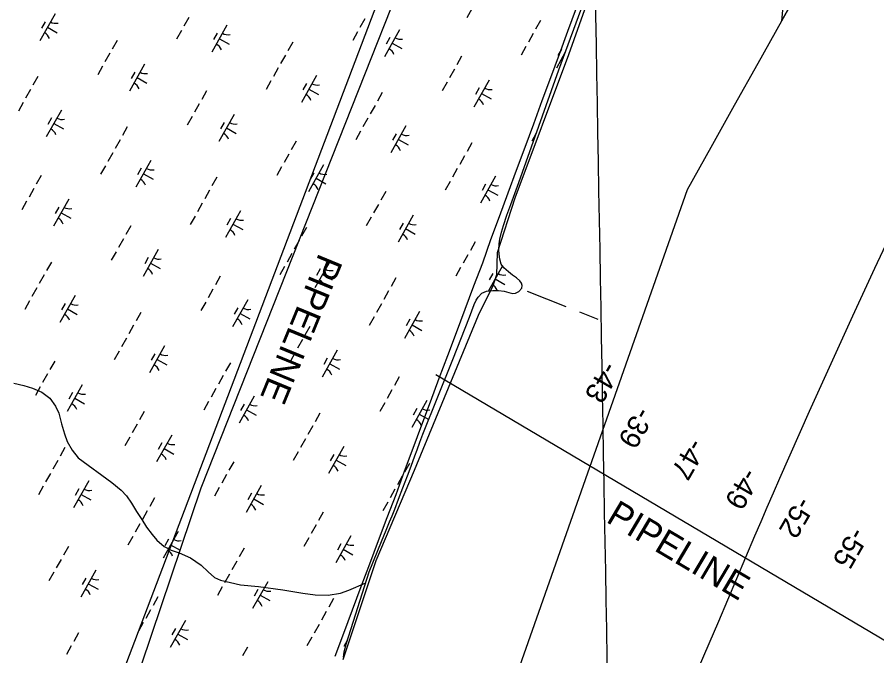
# Model space of a CAD drawing. Extents: x 3913936 to 3933962, y 195330 to 217741.
# Drawn here: x 3924259 to 3925651, y 205982 to 207016 of the extents above; entities that cross this region are included whole.
import ezdxf

# ---------------------------------------------------------------- set-up
doc = ezdxf.new("R2010")
doc.units = 0
for name, color, linetype in [('V-GRID-MAJR', 7, 'Continuous'), ('V-LEVE-TOET', 7, 'Continuous'), ('V-RIVR-EDGE', 7, 'Continuous'), ('V-RIVR-RANG', 7, 'Continuous'), ('V-RRAP-FSHR', 7, 'Continuous'), ('V-TOPO-DPTH', 7, 'Continuous'), ('V-TOPO-MAJR', 7, 'Continuous'), ('V-TOPO-MINR', 7, 'Continuous'), ('V-TOPO-SHOR', 7, 'Continuous'), ('V-UTIL-IDEN', 7, 'Continuous'), ('V-UTIL-LINE', 7, 'Continuous'), ('V-WETL-SWMP', 7, 'Continuous')]:
    doc.layers.add(name, color=color, linetype=linetype)

msp = doc.modelspace()

# ---------------------------------------------------------------- linework, layer by layer
at = {"layer": 'V-GRID-MAJR'}
msp.add_spline([(3925366, 197364), (3925326, 199633.5), (3925219.4, 205693.6), (3925112.7, 211753.6), (3925058.2, 214849.9)], degree=3, dxfattribs=at)
at = {"layer": 'V-LEVE-TOET'}
for p, q in [((3925084.8, 206572.7), (3925147.4, 206548)), ((3925169.6, 206539.2), (3925199.1, 206527.5))]:
    msp.add_line(p, q, dxfattribs=at)
at = {"layer": 'V-RIVR-EDGE'}
msp.add_lwpolyline([(3925251.9, 207238.2), (3925151.7, 206955.3), (3925064.5, 206723.1), (3925036.2, 206634.7), (3925035, 206599.3), (3925029.1, 206581.6), (3925005.6, 206533.3), (3924901.8, 206282.2), (3924839.4, 206136.1), (3924786.3, 205975.8)], dxfattribs=at)
at = {"layer": 'V-RRAP-FSHR'}
for points in [[(3924872.5, 206243.8), (3924886.1, 206281.3), (3924900.2, 206318.7), (3924914.2, 206356.2), (3924928.3, 206393.6), (3924942.3, 206431.8), (3924956.4, 206468.5), (3924970.5, 206506), (3924984.3, 206543.5), (3924998.2, 206581.5), (3925012.8, 206618.5), (3925025.9, 206656.4), (3925039.8, 206693.6), (3925053.7, 206731.8), (3925067.6, 206768.6), (3925081.4, 206806.1), (3925095.3, 206843.6), (3925109.2, 206881.2), (3925123.2, 206918.7), (3925136.9, 206956.2), (3925150.8, 206993.7), (3925164.6, 207031.2)], [(3924773.6, 205981.7), (3924787.7, 206019.2), (3924801.8, 206056.6), (3924815.8, 206094.5), (3924829.9, 206131.5), (3924843.9, 206168.9), (3924858, 206206.4), (3924872.5, 206243.8)]]:
    msp.add_lwpolyline(points, dxfattribs=at)
at = {"layer": 'V-TOPO-DPTH'}
for points in [[(3925522.6, 207291.6), (3925496.5, 207009.8)], [(3925644.4, 207273.5), (3925496.5, 207009.8), (3925458.3, 206941.6), (3925420.2, 206873.4), (3925382.1, 206805.2), (3925344.1, 206736.9), (3924969.1, 205672.3), (3924951.3, 205631.2), (3924933.7, 205590.1), (3924916.4, 205548.8), (3924899.3, 205507.5), (3924874.6, 205447.5), (3924869.9, 205436.1), (3924865.2, 205424.7), (3924860.5, 205413.3), (3924855.8, 205401.9), (3924785.6, 205234.6), (3924745.1, 205139.9), (3924703.8, 205045.5), (3924661.2, 204951.7), (3924617.7, 204858.3), (3924470.8, 204548.4)], [(3925496.5, 207009.8), (3925644.4, 207273.5)]]:
    msp.add_lwpolyline(points, dxfattribs=at)
at = {"layer": 'V-TOPO-MAJR'}
msp.add_lwpolyline([(3925683.3, 206686.1), (3925647.1, 206609.4), (3925611.4, 206532.5), (3925576.3, 206455.3), (3925541.6, 206377.9), (3925493.6, 206269.3), (3925483.3, 206246), (3925473.1, 206222.7), (3925463, 206199.4), (3925453, 206176), (3925394.4, 206038), (3925354.7, 205945.8)], dxfattribs=at)
at = {"layer": 'V-TOPO-MINR'}
msp.add_lwpolyline([(3925644.4, 207273.5), (3925496.5, 207009.8), (3925458.3, 206941.6), (3925420.2, 206873.4), (3925382.1, 206805.2), (3925344.1, 206736.9), (3924969.1, 205672.3), (3924951.3, 205631.2), (3924933.7, 205590.1), (3924916.4, 205548.8), (3924899.3, 205507.5), (3924874.6, 205447.5), (3924869.9, 205436.1), (3924865.2, 205424.7), (3924860.5, 205413.3), (3924855.8, 205401.9), (3924785.6, 205234.6), (3924745.1, 205139.9), (3924703.8, 205045.5), (3924661.2, 204951.7), (3924617.7, 204858.3), (3924470.8, 204548.4)], dxfattribs=at)
at = {"layer": 'V-TOPO-SHOR'}
msp.add_lwpolyline([(3924253.4, 206423.8), (3924269.8, 206420.1), (3924283.8, 206415.6), (3924298.7, 206409.5), (3924311.7, 206399.5), (3924321.1, 206386.7), (3924326.3, 206375), (3924330.7, 206357.9), (3924335.2, 206341.6), (3924339.6, 206329.6), (3924347.9, 206315.2), (3924357.8, 206302.9), (3924411.9, 206262.9), (3924427.2, 206250.5), (3924435.9, 206241.3), (3924444.1, 206229.7), (3924452.1, 206216.1), (3924460.8, 206202.9), (3924468.3, 206190.9), (3924477.3, 206178.9), (3924485.2, 206169.7), (3924497, 206159.2), (3924508.4, 206153.5), (3924520.9, 206149.3), (3924539.3, 206141.3), (3924556.9, 206129.4), (3924568.3, 206118.6), (3924578.5, 206109), (3924587.9, 206104.8), (3924620.7, 206097.3), (3924649.6, 206094.4), (3924689.3, 206089.4), (3924721.3, 206083.8), (3924741.6, 206081.3), (3924762.3, 206080.7), (3924782.5, 206084), (3924796.1, 206088.8), (3924823.3, 206100.4)], dxfattribs=at)
at = {"layer": 'V-UTIL-LINE'}
msp.add_line((3926547, 205483.5), (3924936.8, 206437.1), dxfattribs=at)
for points in [[(3928328.3, 212380.9), (3926784.1, 210502.9), (3926424.7, 209908.7), (3925640.5, 208467.6), (3924952.2, 207329.2), (3923971.7, 204752.2), (3923252.9, 203563.7), (3921560.2, 201558.8), (3920397.9, 200112.9)], [(3928315.8, 212388.1), (3926944.7, 210748.9), (3926592.7, 210251.5), (3926408.9, 209915), (3925628.6, 208474.4), (3925140, 207727.4), (3924556, 206253.6), (3924055.8, 204771.5), (3923484.9, 203858.5), (3922256, 202262.6), (3921816.4, 201905.6), (3920704.8, 200345.1), (3920462.4, 200062.7)]]:
    msp.add_lwpolyline(points, dxfattribs=at)
at = {"layer": 'V-WETL-SWMP'}
for p, q in [((3925135.8, 206930.9), (3925187.8, 207071.5)), ((3925011.5, 207059), (3924987, 207015.4)), ((3924320.2, 207021.8), (3924295.7, 206978.2)), ((3924536.6, 207015.6), (3924528.8, 207001.6)), ((3924304.1, 207009), (3924298.2, 206998.6)), ((3924598.5, 207003.2), (3924574, 206959.7)), ((3924821.8, 207013.6), (3924813.9, 206999.6)), ((3925106.3, 207010.7), (3925098.5, 206996.8)), ((3924307.9, 207000), (3924323.6, 206991.2)), ((3924524.8, 206994.7), (3924517, 206980.7)), ((3924582.5, 206990.5), (3924576.6, 206980)), ((3924810, 206992.7), (3924802.2, 206978.7)), ((3924878.1, 206996), (3924853.6, 206952.4)), ((3925094.6, 206989.8), (3925086.7, 206975.9)), ((3924420.6, 206978.8), (3924412.7, 206964.8)), ((3924586.3, 206981.5), (3924602, 206972.6)), ((3924705.1, 206975.9), (3924697.3, 206962)), ((3924862.1, 206983.2), (3924856.2, 206972.8)), ((3924865.9, 206974.2), (3924881.6, 206965.4)), ((3925082.8, 206968.9), (3925075, 206955)), ((3925146.4, 206959.6), (3925132, 206933.9)), ((3925140.5, 206964.7), (3925134.6, 206954.2)), ((3924408.8, 206957.8), (3924401, 206943.9)), ((3924693.4, 206955), (3924685.5, 206941.1)), ((3924978.5, 206953), (3924970.7, 206939.1)), ((3925144.2, 206955.7), (3925144.9, 206955.3)), ((3924397.1, 206936.9), (3924389.2, 206923)), ((3924465.2, 206940.3), (3924440.7, 206896.7)), ((3924681.6, 206934.1), (3924673.8, 206920.1)), ((3924966.8, 206932.1), (3924958.9, 206918.1)), ((3924292.1, 206920.2), (3924284.3, 206906.2)), ((3924449.1, 206927.5), (3924443.2, 206917)), ((3924452.9, 206918.5), (3924468.6, 206909.7)), ((3924743.5, 206921.7), (3924719, 206878.2)), ((3925071.1, 206748.9), (3925135.8, 206930.9)), ((3924669.8, 206913.2), (3924662, 206899.2)), ((3924727.5, 206909), (3924721.6, 206898.5)), ((3924955, 206911.2), (3924947.2, 206897.2)), ((3925023.1, 206914.5), (3924998.6, 206870.9)), ((3924280.4, 206899.3), (3924272.5, 206885.3)), ((3924565.6, 206897.3), (3924557.7, 206883.3)), ((3924731.3, 206899.9), (3924747, 206891.1)), ((3924850.1, 206894.4), (3924842.3, 206880.5)), ((3925007.1, 206901.7), (3925001.2, 206891.3)), ((3925010.9, 206892.7), (3925026.6, 206883.9)), ((3924268.6, 206878.3), (3924260.8, 206864.4)), ((3924553.8, 206876.3), (3924546, 206862.4)), ((3924330.5, 206866), (3924306, 206822.4)), ((3924838.4, 206873.5), (3924830.5, 206859.6)), ((3924314.5, 206853.2), (3924308.6, 206842.8)), ((3924542.1, 206855.4), (3924534.2, 206841.5)), ((3924610.2, 206858.8), (3924585.6, 206815.2)), ((3924826.6, 206852.6), (3924818.7, 206838.6)), ((3924318.3, 206844.2), (3924334, 206835.4)), ((3924437.1, 206838.7), (3924429.3, 206824.7)), ((3924594.1, 206846), (3924588.2, 206835.5)), ((3924597.9, 206837), (3924613.6, 206828.2)), ((3924888.5, 206840.2), (3924864, 206796.6)), ((3924814.8, 206831.7), (3924807, 206817.7)), ((3924872.5, 206827.4), (3924866.6, 206817)), ((3925099.5, 206828.7), (3925092.2, 206815.7)), ((3924425.4, 206817.8), (3924417.5, 206803.8)), ((3924710.6, 206815.8), (3924702.7, 206801.8)), ((3924876.3, 206818.4), (3924892, 206809.6)), ((3924995.1, 206812.9), (3924987.3, 206799)), ((3924413.6, 206796.8), (3924405.8, 206782.9)), ((3924698.8, 206794.8), (3924691, 206780.9)), ((3924475.5, 206784.5), (3924451, 206740.9)), ((3924983.3, 206792), (3924975.5, 206778)), ((3924401.9, 206775.9), (3924394, 206762)), ((3924459.5, 206771.7), (3924453.6, 206761.2)), ((3924687.1, 206773.9), (3924679.2, 206760)), ((3924755.1, 206777.3), (3924730.6, 206733.7)), ((3924739.1, 206764.5), (3924733.2, 206754)), ((3924971.6, 206771.1), (3924963.7, 206757.1)), ((3924297.6, 206760), (3924289.8, 206746.1)), ((3924463.3, 206762.7), (3924479, 206753.9)), ((3924582.1, 206757.2), (3924574.3, 206743.2)), ((3924742.9, 206755.5), (3924758.6, 206746.7)), ((3925033.5, 206758.7), (3925009, 206715.1)), ((3924285.8, 206739.1), (3924278, 206725.1)), ((3924959.8, 206750.1), (3924952, 206736.2)), ((3925017.5, 206745.9), (3925011.6, 206735.5)), ((3925021.3, 206736.9), (3925037, 206728.1)), ((3925058.1, 206713.2), (3925071.1, 206748.9)), ((3924570.4, 206736.3), (3924562.5, 206722.3)), ((3924855.6, 206734.2), (3924847.7, 206720.3)), ((3924274.1, 206718.2), (3924266.2, 206704.2)), ((3924342.2, 206721.5), (3924317.7, 206677.9)), ((3924326.1, 206708.7), (3924320.3, 206698.3)), ((3924558.6, 206715.3), (3924550.8, 206701.4)), ((3924843.8, 206713.3), (3924836, 206699.4)), ((3925052, 206695.9), (3925058.1, 206713.2)), ((3924329.9, 206699.7), (3924345.6, 206690.9)), ((3924620.5, 206703), (3924596, 206659.4)), ((3924900.1, 206695.8), (3924875.6, 206652.2)), ((3925046.2, 206679.1), (3925052, 206695.9)), ((3924546.9, 206694.4), (3924539, 206680.5)), ((3924604.5, 206690.2), (3924598.6, 206679.7)), ((3924608.3, 206681.2), (3924624, 206672.4)), ((3924832, 206692.4), (3924824.2, 206678.5)), ((3924884.1, 206683), (3924878.2, 206672.5)), ((3924442.6, 206678.5), (3924434.8, 206664.6)), ((3924727.1, 206675.7), (3924719.3, 206661.7)), ((3924887.9, 206674), (3924903.6, 206665.1)), ((3925040.4, 206657.1), (3925042.9, 206668.4)), ((3925042.9, 206668.4), (3925046.2, 206679.1)), ((3924430.8, 206657.6), (3924423, 206643.6)), ((3924715.4, 206654.7), (3924707.5, 206640.8)), ((3925039.6, 206649.5), (3925040.4, 206657.1)), ((3924487.2, 206640), (3924462.7, 206596.4)), ((3925000.6, 206652.7), (3924992.7, 206638.8)), ((3925038.7, 206639.9), (3925039.6, 206649.5)), ((3925039.3, 206632.5), (3925038.7, 206639.9)), ((3924419.1, 206636.7), (3924411.2, 206622.7)), ((3924471.1, 206627.2), (3924465.3, 206616.8)), ((3924703.6, 206633.8), (3924695.8, 206619.9)), ((3924988.8, 206631.8), (3924981, 206617.9)), ((3925040.7, 206624.5), (3925039.3, 206632.5)), ((3924314.2, 206619.9), (3924306.3, 206606)), ((3924474.9, 206618.2), (3924490.6, 206609.4)), ((3924691.9, 206612.9), (3924684, 206599)), ((3924765.5, 206621.5), (3924741, 206577.9)), ((3925044.8, 206613.7), (3925022, 206573.1)), ((3925042.8, 206616.6), (3925040.7, 206624.5)), ((3925046.8, 206610.7), (3925042.8, 206616.6)), ((3924302.4, 206599), (3924294.6, 206585.1)), ((3924749.5, 206608.7), (3924743.6, 206598.2)), ((3924753.3, 206599.7), (3924769, 206590.9)), ((3924977, 206610.9), (3924969.2, 206596.9)), ((3925029.1, 206601.5), (3925023.2, 206591)), ((3925054.4, 206603.9), (3925046.8, 206610.7)), ((3925061, 206598.8), (3925054.4, 206603.9)), ((3925067.3, 206594.4), (3925061, 206598.8)), ((3924587.6, 206597), (3924579.8, 206583)), ((3924872.1, 206594.2), (3924864.3, 206580.2)), ((3925032.9, 206592.5), (3925048.6, 206583.6)), ((3925073.1, 206589.7), (3925067.3, 206594.4)), ((3925075.8, 206585.6), (3925073.1, 206589.7)), ((3925076.6, 206581.7), (3925075.8, 206585.6)), ((3924290.6, 206578.1), (3924282.8, 206564.1)), ((3924575.8, 206576.1), (3924568, 206562.1)), ((3924860.4, 206573.2), (3924852.5, 206559.3)), ((3925011.4, 206569.3), (3925018.9, 206572.8)), ((3925018.9, 206572.8), (3925029.4, 206573.9)), ((3925029.4, 206573.9), (3925038.3, 206574)), ((3925038.3, 206574), (3925047.4, 206572.5)), ((3925047.4, 206572.5), (3925055, 206570.7)), ((3925055, 206570.7), (3925061.3, 206569.2)), ((3925061.3, 206569.2), (3925066, 206569.5)), ((3925066, 206569.5), (3925071.2, 206572.2)), ((3925071.2, 206572.2), (3925076.1, 206577.5)), ((3925076.1, 206577.5), (3925076.6, 206581.7)), ((3924278.9, 206557.2), (3924271, 206543.2)), ((3924352.6, 206565.7), (3924328.1, 206522.1)), ((3924632.2, 206558.5), (3924607.7, 206514.9)), ((3924998.7, 206551.4), (3925002.1, 206558.2)), ((3925002.1, 206558.2), (3925005.2, 206563.2)), ((3925005.2, 206563.2), (3925011.4, 206569.3)), ((3924336.5, 206552.9), (3924330.7, 206542.5)), ((3924340.3, 206543.9), (3924356, 206535.1)), ((3924564.1, 206555.2), (3924556.2, 206541.2)), ((3924616.1, 206545.7), (3924610.3, 206535.3)), ((3924848.6, 206552.3), (3924840.8, 206538.4)), ((3924991.6, 206530.9), (3924998.7, 206551.4)), ((3924459.2, 206538.4), (3924451.3, 206524.5)), ((3924619.9, 206536.7), (3924635.6, 206527.9)), ((3924836.9, 206531.4), (3924829, 206517.4)), ((3924910.5, 206540), (3924886, 206496.4)), ((3924964.6, 206462), (3924991.6, 206530.9)), ((3924447.4, 206517.5), (3924439.6, 206503.5)), ((3924732.6, 206515.5), (3924724.8, 206501.5)), ((3924894.5, 206527.2), (3924888.6, 206516.7)), ((3924898.3, 206518.2), (3924914, 206509.3)), ((3924435.6, 206496.6), (3924427.8, 206482.6)), ((3924720.8, 206494.6), (3924713, 206480.6)), ((3924423.9, 206475.6), (3924416, 206461.7)), ((3924497.6, 206484.2), (3924473.1, 206440.6)), ((3924709.1, 206473.6), (3924701.2, 206459.7)), ((3924777.2, 206477), (3924752.7, 206433.4)), ((3924319.6, 206459.7), (3924311.8, 206445.8)), ((3924481.5, 206471.4), (3924475.7, 206461)), ((3924485.3, 206462.4), (3924501, 206453.6)), ((3924761.1, 206464.2), (3924755.3, 206453.8)), ((3924915.8, 206341.3), (3924964.6, 206462)), ((3924604.2, 206456.9), (3924596.3, 206443)), ((3924764.9, 206455.2), (3924780.6, 206446.4)), ((3924307.9, 206438.8), (3924300, 206424.9)), ((3924592.4, 206436), (3924584.6, 206422)), ((3924877.6, 206434), (3924869.8, 206420)), ((3924296.1, 206417.9), (3924288.3, 206404)), ((3924364.2, 206421.3), (3924339.7, 206377.7)), ((3924348.2, 206408.5), (3924342.3, 206398)), ((3924580.6, 206415.1), (3924572.8, 206401.1)), ((3924642.6, 206402.7), (3924618.1, 206359.1)), ((3924865.8, 206413.1), (3924858, 206399.1)), ((3924352, 206399.5), (3924367.6, 206390.6)), ((3924568.9, 206394.1), (3924561, 206380.2)), ((3924626.5, 206389.9), (3924620.7, 206379.5)), ((3924854.1, 206392.1), (3924846.2, 206378.2)), ((3924922.2, 206395.5), (3924897.7, 206351.9)), ((3924464.6, 206378.2), (3924456.8, 206364.3)), ((3924630.3, 206380.9), (3924646, 206372.1)), ((3924749.2, 206375.4), (3924741.3, 206361.4)), ((3924906.1, 206382.7), (3924900.3, 206372.2)), ((3924909.9, 206373.7), (3924925.4, 206365)), ((3924452.9, 206357.3), (3924445, 206343.4)), ((3924737.4, 206354.5), (3924729.6, 206340.5)), ((3924441.1, 206336.4), (3924433.3, 206322.4)), ((3924509.2, 206339.7), (3924484.7, 206296.2)), ((3924725.6, 206333.6), (3924717.8, 206319.6)), ((3924910.9, 206328.1), (3924915.8, 206341.3)), ((3924336.2, 206319.7), (3924328.4, 206305.7)), ((3924493.2, 206327), (3924487.3, 206316.5)), ((3924787.6, 206321.2), (3924763.1, 206277.6)), ((3924906.6, 206315.8), (3924910.9, 206328.1)), ((3924497, 206318), (3924512.6, 206309.1)), ((3924713.9, 206312.6), (3924706, 206298.7)), ((3924771.5, 206308.4), (3924765.7, 206298)), ((3924896.9, 206289.3), (3924902.8, 206306.1)), ((3924902.8, 206306.1), (3924906.6, 206315.8)), ((3924324.4, 206298.7), (3924316.6, 206284.8)), ((3924609.6, 206296.7), (3924601.8, 206282.8)), ((3924775.3, 206299.4), (3924791, 206290.6)), ((3924894.2, 206293.9), (3924886.3, 206279.9)), ((3924312.7, 206277.8), (3924304.8, 206263.9)), ((3924891, 206273.9), (3924896.9, 206289.3)), ((3924374.6, 206265.5), (3924350.1, 206221.9)), ((3924597.9, 206275.8), (3924590, 206261.9)), ((3924882.4, 206273), (3924874.6, 206259)), ((3924883.6, 206254.4), (3924891, 206273.9)), ((3924300.9, 206256.9), (3924293.1, 206242.9)), ((3924358.6, 206252.7), (3924352.7, 206242.2)), ((3924586.1, 206254.9), (3924578.3, 206240.9)), ((3924654.2, 206258.2), (3924629.7, 206214.7)), ((3924870.6, 206252), (3924862.8, 206238.1)), ((3924876.2, 206235.8), (3924883.6, 206254.4)), ((3924362.3, 206243.7), (3924378, 206234.8)), ((3924481.2, 206238.1), (3924473.4, 206224.2)), ((3924638.2, 206245.5), (3924632.3, 206235)), ((3924641.9, 206236.4), (3924657.6, 206227.6)), ((3924870.4, 206220.1), (3924876.2, 206235.8)), ((3924858.9, 206231.1), (3924851, 206217.2)), ((3924469.4, 206217.2), (3924461.6, 206203.3)), ((3924754.6, 206215.2), (3924746.8, 206201.3)), ((3924861.7, 206199.1), (3924866, 206209.3)), ((3924866, 206209.3), (3924870.4, 206220.1)), ((3924457.7, 206196.3), (3924449.8, 206182.4)), ((3924742.9, 206194.3), (3924735, 206180.3)), ((3924856.3, 206185.7), (3924861.7, 206199.1)), ((3924519.6, 206183.9), (3924495.1, 206140.4)), ((3924848.6, 206167.6), (3924856.3, 206185.7)), ((3924445.9, 206175.4), (3924438.1, 206161.4)), ((3924503.6, 206171.2), (3924497.7, 206160.7)), ((3924731.1, 206173.4), (3924723.3, 206159.4)), ((3924799.2, 206176.7), (3924774.7, 206133.1)), ((3924829, 206118.3), (3924848.6, 206167.6)), ((3924341.7, 206159.5), (3924333.8, 206145.5)), ((3924507.3, 206162.2), (3924523, 206153.3)), ((3924626.2, 206156.6), (3924618.3, 206142.7)), ((3924783.2, 206163.9), (3924777.3, 206153.5)), ((3924786.9, 206154.9), (3924802.6, 206146.1)), ((3924329.9, 206138.6), (3924322.1, 206124.6)), ((3924614.4, 206135.7), (3924606.6, 206121.8)), ((3924318.1, 206117.6), (3924310.3, 206103.7)), ((3924386.2, 206121), (3924361.7, 206077.4)), ((3924602.7, 206114.8), (3924594.8, 206100.8)), ((3924792.2, 206002.9), (3924829, 206118.3)), ((3924370.2, 206108.2), (3924364.3, 206097.7)), ((3924374, 206099.2), (3924389.7, 206090.4)), ((3924664.6, 206102.4), (3924640.1, 206058.9)), ((3924590.9, 206093.9), (3924583.1, 206079.9)), ((3924648.6, 206089.7), (3924642.7, 206079.2)), ((3924486.7, 206078), (3924478.8, 206064)), ((3924652.3, 206080.6), (3924668, 206071.8)), ((3924771.2, 206075.1), (3924763.3, 206061.2)), ((3924474.9, 206057), (3924467, 206043.1)), ((3924759.4, 206054.2), (3924751.6, 206040.3)), ((3924463.1, 206036.1), (3924455.3, 206022.2)), ((3924531.2, 206039.5), (3924506.7, 205995.9)), ((3924515.2, 206026.7), (3924509.3, 206016.2)), ((3924747.7, 206033.3), (3924739.8, 206019.3)), ((3924358.2, 206019.4), (3924350.4, 206005.4)), ((3924519, 206017.7), (3924534.7, 206008.9)), ((3924735.9, 206012.4), (3924728.1, 205998.4)), ((3924793.6, 206008.1), (3924787.7, 205997.7)), ((3924788.6, 205989), (3924792.2, 206002.9)), ((3924346.5, 205998.5), (3924338.6, 205984.5)), ((3924631.6, 205996.5), (3924623.8, 205982.5)), ((3924787.4, 205980.1), (3924788.6, 205989))]:
    msp.add_line(p, q, dxfattribs=at)
for centre, start, end in [((3924321.6, 207024), 239.8861, 281.4297), ((3924294.6, 206975.8), 19.8861, 61.4297), ((3924600, 207005.4), 239.8861, 281.4297), ((3924879.6, 206998.2), 239.8861, 281.4297), ((3924572.9, 206957.3), 19.8861, 61.4297), ((3924852.5, 206950), 19.8861, 61.4297), ((3925130.9, 206931.5), 53.873, 61.4297), ((3924466.6, 206942.5), 239.8861, 281.4297), ((3924439.6, 206894.3), 19.8861, 61.4297), ((3924745, 206923.9), 239.8861, 281.4297), ((3924717.9, 206875.7), 19.8861, 61.4297), ((3925024.6, 206916.7), 239.8861, 281.4297), ((3924997.5, 206868.5), 19.8861, 61.4297), ((3924332, 206868.2), 239.8861, 281.4297), ((3924305, 206820), 19.8861, 61.4297), ((3924611.6, 206860.9), 239.8861, 281.4297), ((3924584.6, 206812.8), 19.8861, 61.4297), ((3924890, 206842.4), 239.8861, 281.4297), ((3924862.9, 206794.2), 19.8861, 61.4297), ((3924477, 206786.7), 239.8861, 281.4297), ((3924450, 206738.5), 19.8861, 61.4297), ((3924756.6, 206779.4), 239.8861, 281.4297), ((3924729.6, 206731.3), 19.8861, 61.4297), ((3925035, 206760.9), 239.8861, 281.4297), ((3925007.9, 206712.7), 19.8861, 61.4297), ((3924343.7, 206723.7), 239.8861, 281.4297), ((3924316.6, 206675.5), 19.8861, 61.4297), ((3924622, 206705.1), 239.8861, 281.4297), ((3924901.6, 206697.9), 239.8861, 281.4297), ((3924595, 206657), 19.8861, 61.4297), ((3924874.6, 206649.8), 19.8861, 61.4297), ((3924488.7, 206642.2), 239.8861, 281.4297), ((3924461.6, 206594), 19.8861, 61.4297), ((3924767, 206623.6), 239.8861, 281.4297), ((3925046.6, 206616.4), 239.8861, 281.4297), ((3924740, 206575.5), 19.8861, 61.4297), ((3925019.6, 206568.3), 19.8861, 61.4297), ((3924354.1, 206567.9), 239.8861, 281.4297), ((3924633.7, 206560.7), 239.8861, 281.4297), ((3924327, 206519.7), 19.8861, 61.4297), ((3924606.6, 206512.5), 19.8861, 61.4297), ((3924912, 206542.1), 239.8861, 281.4297), ((3924885, 206494), 19.8861, 61.4297), ((3924499.1, 206486.4), 239.8861, 281.4297), ((3924778.7, 206479.2), 239.8861, 281.4297), ((3924472, 206438.2), 19.8861, 61.4297), ((3924751.6, 206431), 19.8861, 61.4297), ((3924365.7, 206423.4), 239.8861, 281.4297), ((3924338.6, 206375.3), 19.8861, 61.4297), ((3924644.1, 206404.9), 239.8861, 281.4297), ((3924923.7, 206397.7), 239.8861, 281.4297), ((3924617, 206356.7), 19.8861, 61.4297), ((3924896.6, 206349.5), 19.8861, 61.4297), ((3924510.7, 206341.9), 239.8861, 281.4297), ((3924483.6, 206293.8), 19.8861, 61.4297), ((3924789.1, 206323.4), 239.8861, 281.4297), ((3924762, 206275.2), 19.8861, 61.4297), ((3924376.1, 206267.6), 239.8861, 281.4297), ((3924655.7, 206260.4), 239.8861, 281.4297), ((3924349, 206219.5), 19.8861, 61.4297), ((3924628.6, 206212.3), 19.8861, 61.4297), ((3924521.1, 206186.1), 239.8861, 281.4297), ((3924494, 206138), 19.8861, 61.4297), ((3924800.7, 206178.9), 239.8861, 281.4297), ((3924773.6, 206130.7), 19.8861, 61.4297), ((3924387.7, 206123.2), 239.8861, 281.4297), ((3924360.7, 206075), 19.8861, 61.4297), ((3924666.1, 206104.6), 239.8861, 281.4297), ((3924639, 206056.5), 19.8861, 61.4297), ((3924532.7, 206041.6), 239.8861, 281.4297), ((3924505.6, 205993.5), 19.8861, 61.4297)]:
    msp.add_arc(centre, 17.6, start, end, dxfattribs=at)

# ---------------------------------------------------------------- texts
at = {"layer": 'V-RIVR-RANG'}
for s, rotation, p in [('-43', 239.9083, (3925209.2, 206461)), ('-39', 240.0512, (3925263.3, 206387.6)), ('-47', 240.0512, (3925348.4, 206336.7)), ('-49', 240.0512, (3925435.9, 206288.6)), ('-52', 240.0512, (3925523.6, 206242.2)), ('-55', 240.0512, (3925610.5, 206192.8))]:
    msp.add_text(s, height=33.5, rotation=rotation, dxfattribs=at).set_placement(p)
at = {"layer": 'V-UTIL-IDEN'}
for s, rotation, p in [('PIPELINE', 247.6475, (3924748, 206635.8)), (' PIPELINE', 329.3374, (3925197.4, 206207.9))]:
    msp.add_text(s, height=42, rotation=rotation, dxfattribs=at).set_placement(p)

doc.saveas('drawing.dxf')
